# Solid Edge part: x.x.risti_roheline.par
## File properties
Author: Romil
Template: iso part.par
Last saved by: Romil
Revision: 43
Application: Solid Edge
Accuracy: 0.990
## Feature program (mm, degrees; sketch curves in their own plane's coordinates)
sketch for "unnamed Protrusion 1" plane through (0, 0, 0) normal (1, 0, 0) x-axis (0, 1, 0)
extrude "unnamed Protrusion 1" add finite 7.8 symmetric
sketch for "unnamed RevolvedCutout 1" plane through (0, 0, 0) normal (0, -1, 0) x-axis (1, 0, 0)
revolve "unnamed RevolvedCutout 1" cut finite 360 deg
sketch for "ExtrudedProtrusion_11" plane through (0, 0, 11.6) normal (0, 0, 1) x-axis (1, 0, 0)
extrude "ExtrudedProtrusion_11" add finite 6.8 along -normal
sketch for "unnamed Protrusion 2" plane through (0, 0, 11.6) normal (0, 0, 1) x-axis (1, 0, 0)
extrude "unnamed Protrusion 2" add finite 1.2 along -normal
sketch for "unnamed Protrusion 3" plane through (0, 0, 0) normal (0, 0, 1) x-axis (1, 0, 0)
extrude "unnamed Protrusion 3" add to key point along +normal
sketch for "unnamed Protrusion 4" plane through (0, 0, 0) normal (0, 0, 1) x-axis (1, 0, 0)
extrude "unnamed Protrusion 4" add to key point along +normal
mirror "unnamed Mirror 1" of "unnamed Protrusion 3" about plane through (0, 0, 0) normal (1, 0, 0)
extrude "unnamed Protrusion 5" add finite 4.8
sketch used by "unnamed Protrusion 6" plane through (0, 0, 0) normal (0, -1, 0) x-axis (1, 0, 0)
extrude "unnamed Protrusion 6" add to key point symmetric
sketch for "unnamed Cutout 1" plane through (0, 0, 11.6) normal (0, 0, 1) x-axis (1, 0, 0)
extrude "unnamed Cutout 1" cut to key point symmetric
sketch for "unnamed Cutout 2" plane through (0, 0, 0) normal (1, 0, 0) x-axis (0, 1, 0)
extrude "unnamed Cutout 2" cut finite 47.4999 symmetric
sketch for "ExtrudedCutout_25" plane through (0, 0, 0) normal (0, -1, 0) x-axis (1, 0, 0)
  circle centre (0, 0) radius 3.6
extrude "ExtrudedCutout_25" cut finite 152.9831 symmetric
sketch used by "ExtrudedCutout_26" plane through (0, 0, 0) normal (0, -1, 0) x-axis (1, 0, 0)
  line (0.6, 9.8798) -> (0.6, 5.3861)
  line (-0.6, 5.3861) -> (-0.6, 9.8798)
  line (0.6, 5.3861) -> (0.6, 4.8)
  line (0.6, 4.8) -> (-0.6, 4.8)
  line (-0.6, 4.8) -> (-0.6, 5.3861)
  line (-0.6, 9.8798) -> (-0.6, 10.4)
  line (-0.6, 10.4) -> (0.6, 10.4)
  line (0.6, 10.4) -> (0.6, 9.8798)
extrude "ExtrudedCutout_26" cut finite 35.3769 symmetric
fillet "unnamed Round 1"
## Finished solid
Body 1: solid body, 120 faces, 320 edges, 200 vertices.
  Faces by surface: cylinder 63, plane 43, blend 12, torus 2
  Edges by curve: line 170, circle 94, intersection 32, ellipse 24
Bounding box of the edges (mm; curved faces can reach further): 7.800 x 7.200 x 15.200, from (-3.9, -3.6, -3.6) to (3.9, 3.6, 11.6).
Cylindrical faces by radius (mm): R0.1 x8, R0.2 x8, R0.4 x24, R2.2319 x4, R2.35 x8, R2.7009 x2, R3.0587 x3, R3.6 x6
Toroidal faces (ring radius, tube radius in mm): R3.3 r0.3 x2
Planar faces by outward normal: +x 9, +y 6, +z 6, -x 9, -y 6, -z 7
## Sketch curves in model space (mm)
arc centre (0.975, -0.975, 11.6) radius 0.1 from (0.875, -0.975, 11.6) through (0.9064, -0.9023, 11.6) to (0.975, -0.875, 11.6)
line (0.975, -0.875, 11.6) -> (2.181, -0.875, 11.6)
arc centre (0, 0, 11.6) radius 2.35 from (2.181, 0.875, 11.6) through (2.35, 0, 11.6) to (2.181, -0.875, 11.6)
line (2.181, 0.875, 11.6) -> (0.975, 0.875, 11.6)
arc centre (0.975, 0.975, 11.6) radius 0.1 from (0.975, 0.875, 11.6) through (0.9023, 0.9064, 11.6) to (0.875, 0.975, 11.6)
line (0.875, 0.975, 11.6) -> (0.875, 2.181, 11.6)
arc centre (0, 0, 11.6) radius 2.35 from (-0.875, 2.181, 11.6) through (0, 2.35, 11.6) to (0.875, 2.181, 11.6)
line (-0.875, 2.181, 11.6) -> (-0.875, 0.975, 11.6)
arc centre (-0.975, 0.975, 11.6) radius 0.1 from (-0.875, 0.975, 11.6) through (-0.9064, 0.9023, 11.6) to (-0.975, 0.875, 11.6)
line (-0.975, 0.875, 11.6) -> (-2.181, 0.875, 11.6)
arc centre (0, 0, 11.6) radius 2.35 from (-2.181, -0.875, 11.6) through (-2.35, 0, 11.6) to (-2.181, 0.875, 11.6)
line (-2.181, -0.875, 11.6) -> (-0.975, -0.875, 11.6)
arc centre (-0.975, -0.975, 11.6) radius 0.1 from (-0.975, -0.875, 11.6) through (-0.9023, -0.9064, 11.6) to (-0.875, -0.975, 11.6)
line (-0.875, -0.975, 11.6) -> (-0.875, -2.181, 11.6)
arc centre (0, 0, 11.6) radius 2.35 from (0.875, -2.181, 11.6) through (0, -2.35, 11.6) to (-0.875, -2.181, 11.6)
line (0.875, -2.181, 11.6) -> (0.875, -0.975, 11.6)
circle centre (0, 0, 11.6) radius 2.7009
arc centre (-0.975, -0.975, 0) radius 0.1 from (-0.975, -0.875, 0) through (-0.9023, -0.9064, 0) to (-0.875, -0.975, 0)
line (-0.875, -0.975, 0) -> (-0.875, -2.181, 0)
arc centre (0, 0, 0) radius 2.35 from (0.875, -2.181, 0) through (0, -2.35, 0) to (-0.875, -2.181, 0)
line (0.875, -2.181, 0) -> (0.875, -0.975, 0)
arc centre (0.975, -0.975, 0) radius 0.1 from (0.875, -0.975, 0) through (0.9064, -0.9023, 0) to (0.975, -0.875, 0)
line (0.975, -0.875, 0) -> (2.181, -0.875, 0)
arc centre (0, 0, 0) radius 2.35 from (2.181, 0.875, 0) through (2.35, 0, 0) to (2.181, -0.875, 0)
line (2.181, 0.875, 0) -> (0.975, 0.875, 0)
arc centre (0.975, 0.975, 0) radius 0.1 from (0.975, 0.875, 0) through (0.9023, 0.9064, 0) to (0.875, 0.975, 0)
line (0.875, 0.975, 0) -> (0.875, 2.181, 0)
arc centre (0, 0, 0) radius 2.35 from (-0.875, 2.181, 0) through (0, 2.35, 0) to (0.875, 2.181, 0)
line (-0.875, 2.181, 0) -> (-0.875, 0.975, 0)
arc centre (-0.975, 0.975, 0) radius 0.1 from (-0.875, 0.975, 0) through (-0.9064, 0.9023, 0) to (-0.975, 0.875, 0)
line (-0.975, 0.875, 0) -> (-2.181, 0.875, 0)
arc centre (0, 0, 0) radius 2.35 from (-2.181, -0.875, 0) through (-2.35, 0, 0) to (-2.181, 0.875, 0)
line (-2.181, -0.875, 0) -> (-0.975, -0.875, 0)
arc centre (1.1947, 3.1832, 0) radius 0.2 from (1.3919, 3.2163, 0) through (1.349, 3.3104, 0) to (1.2649, 3.3705, 0)
arc centre (3.593, 3.586, 0) radius 2.2319 from (3.219, 1.3856, 0) through (1.9675, 2.0565, 0) to (1.3919, 3.2163, 0)
arc centre (3.1855, 1.1884, 0) radius 0.2 from (3.3729, 1.2583, 0) through (3.313, 1.3425, 0) to (3.219, 1.3856, 0)
arc centre (0, 0, 0) radius 3.6 from (3.3729, 1.2583, 0) through (3.6, 0, 0) to (3.3729, -1.2583, 0)
arc centre (3.1855, -1.1884, 0) radius 0.2 from (3.219, -1.3856, 0) through (3.313, -1.3425, 0) to (3.3729, -1.2583, 0)
arc centre (3.593, -3.586, 0) radius 2.2319 from (3.219, -1.3856, 0) through (1.9675, -2.0565, 0) to (1.3919, -3.2163, 0)
arc centre (1.1947, -3.1832, 0) radius 0.2 from (1.2649, -3.3705, 0) through (1.349, -3.3104, 0) to (1.3919, -3.2163, 0)
arc centre (0, 0, 0) radius 3.6 from (1.2649, -3.3705, 0) through (0, -3.6, 0) to (-1.2649, -3.3705, 0)
arc centre (-1.1947, -3.1832, 0) radius 0.2 from (-1.3919, -3.2163, 0) through (-1.349, -3.3104, 0) to (-1.2649, -3.3705, 0)
arc centre (-3.593, -3.586, 0) radius 2.2319 from (-3.219, -1.3856, 0) through (-1.9675, -2.0565, 0) to (-1.3919, -3.2163, 0)
arc centre (-3.1855, -1.1884, 0) radius 0.2 from (-3.3729, -1.2583, 0) through (-3.313, -1.3425, 0) to (-3.219, -1.3856, 0)
arc centre (0, 0, 0) radius 3.6 from (-3.3729, -1.2583, 0) through (-3.6, 0, 0) to (-3.3729, 1.2583, 0)
arc centre (-3.1855, 1.1884, 0) radius 0.2 from (-3.219, 1.3856, 0) through (-3.313, 1.3425, 0) to (-3.3729, 1.2583, 0)
arc centre (-3.593, 3.586, 0) radius 2.2319 from (-3.219, 1.3856, 0) through (-1.9675, 2.0565, 0) to (-1.3919, 3.2163, 0)
arc centre (-1.1947, 3.1832, 0) radius 0.2 from (-1.2649, 3.3705, 0) through (-1.349, 3.3104, 0) to (-1.3919, 3.2163, 0)
arc centre (0, 0, 0) radius 3.6 from (-1.2649, 3.3705, 0) through (0, 3.6, 0) to (1.2649, 3.3705, 0)
line (3.6217, 0, 4.8) -> (3.6217, 0, 3.8)
line (3.6217, 0, 3.8) -> (-3.6217, 0, 3.8)
line (-3.6217, 0, 3.8) -> (-3.6217, 0, 4.8)
line (-3.6217, 0, 4.8) -> (3.6217, 0, 4.8)
line (2.7, 0, -0.6) -> (2.7, 0, 0.6)
line (2.7, 0, 0.6) -> (-2.7, 0, 0.6)
line (-2.7, 0, 0.6) -> (-2.7, 0, -0.6)
line (-2.7, 0, -0.6) -> (2.7, 0, -0.6)
line (-3.35, -0.6, 0) -> (-3.35, 0.6, 0)
line (-3.35, 0.6, 0) -> (3.35, 0.6, 0)
line (3.35, 0.6, 0) -> (3.35, -0.6, 0)
line (3.35, -0.6, 0) -> (-3.35, -0.6, 0)
line (0.6, 0, 5.3861) -> (0.6, 0, 4.8)
line (0.6, 0, 4.8) -> (-0.6, 0, 4.8)
line (-0.6, 0, 4.8) -> (-0.6, 0, 5.3861)
line (-0.6, 0, 5.3861) -> (-0.6, 0, 9.8798)
line (-0.6, 0, 9.8798) -> (-0.6, 0, 10.4)
line (-0.6, 0, 10.4) -> (0.6, 0, 10.4)
line (0.6, 0, 10.4) -> (0.6, 0, 9.8798)
line (0.6, 0, 9.8798) -> (0.6, 0, 5.3861)
line (-4.4651, 0, 0) -> (5.0671, 0, 0)
line (2.7, 0, 3.0587) -> (2.7, 0, 3.3)
arc centre (3, 0, 3.3) radius 0.3 from (2.7, 0, 3.3) through (2.7941, 0, 3.5182) to (3, 0, 3.6)
line (3, 0, 3.6) -> (3.9, 0, 3.6)
line (3.9, 0, 3.6) -> (3.9, 0, 4.041)
line (3.9, 0, 4.041) -> (-3.9, 0, 4.041)
line (-3.9, 0, 4.041) -> (-3.9, 0, 3.6)
line (-3.9, 0, 3.6) -> (-3, 0, 3.6)
arc centre (-3, 0, 3.3) radius 0.3 from (-2.7, 0, 3.3) through (-2.7941, 0, 3.5182) to (-3, 0, 3.6)
line (-2.7, 0, 3.3) -> (-2.7, 0, 3.0587)
line (-2.7, 0, 3.0587) -> (2.7, 0, 3.0587)
circle centre (0, 0, 7.9783) radius 2.4
circle centre (0, 0, 7.9783) radius 3.6217
line (-3.6217, -2.75, 0) -> (-3.6217, 1.953, 0)
line (-3.6217, -2.75, 0) -> (-2.7879, -2.75, 0)
line (-2.7879, 2.75, 0) -> (-2.7879, -2.75, 0)
line (-3.6217, 2.75, 0) -> (-2.7879, 2.75, 0)
line (-3.6217, 2.75, 0) -> (-3.6217, 1.953, 0)
circle centre (0, 0, 0) radius 3.6
arc centre (3.593, -3.586, 11.6) radius 2.2319 from (3.219, -1.3856, 11.6) through (1.9675, -2.0565, 11.6) to (1.3919, -3.2163, 11.6)
arc centre (3.1855, -1.1884, 11.6) radius 0.2 from (3.219, -1.3856, 11.6) through (3.313, -1.3425, 11.6) to (3.3729, -1.2583, 11.6)
arc centre (0, 0, 11.6) radius 3.6 from (3.3729, 1.2583, 11.6) through (3.6, 0, 11.6) to (3.3729, -1.2583, 11.6)
arc centre (3.1855, 1.1884, 11.6) radius 0.2 from (3.3729, 1.2583, 11.6) through (3.313, 1.3425, 11.6) to (3.219, 1.3856, 11.6)
arc centre (3.593, 3.586, 11.6) radius 2.2319 from (3.219, 1.3856, 11.6) through (1.9675, 2.0565, 11.6) to (1.3919, 3.2163, 11.6)
arc centre (1.1947, 3.1832, 11.6) radius 0.2 from (1.3919, 3.2163, 11.6) through (1.349, 3.3104, 11.6) to (1.2649, 3.3705, 11.6)
arc centre (0, 0, 11.6) radius 3.6 from (-1.2649, 3.3705, 11.6) through (0, 3.6, 11.6) to (1.2649, 3.3705, 11.6)
arc centre (-1.1947, 3.1832, 11.6) radius 0.2 from (-1.2649, 3.3705, 11.6) through (-1.349, 3.3104, 11.6) to (-1.3919, 3.2163, 11.6)
arc centre (-3.593, 3.586, 11.6) radius 2.2319 from (-3.219, 1.3856, 11.6) through (-1.9675, 2.0565, 11.6) to (-1.3919, 3.2163, 11.6)
arc centre (-3.1855, 1.1884, 11.6) radius 0.2 from (-3.219, 1.3856, 11.6) through (-3.313, 1.3425, 11.6) to (-3.3729, 1.2583, 11.6)
arc centre (0, 0, 11.6) radius 3.6 from (-3.3729, -1.2583, 11.6) through (-3.6, 0, 11.6) to (-3.3729, 1.2583, 11.6)
arc centre (-3.1855, -1.1884, 11.6) radius 0.2 from (-3.3729, -1.2583, 11.6) through (-3.313, -1.3425, 11.6) to (-3.219, -1.3856, 11.6)
arc centre (-3.593, -3.586, 11.6) radius 2.2319 from (-3.219, -1.3856, 11.6) through (-1.9675, -2.0565, 11.6) to (-1.3919, -3.2163, 11.6)
arc centre (-1.1947, -3.1832, 11.6) radius 0.2 from (-1.3919, -3.2163, 11.6) through (-1.349, -3.3104, 11.6) to (-1.2649, -3.3705, 11.6)
arc centre (0, 0, 11.6) radius 3.6 from (1.2649, -3.3705, 11.6) through (0, -3.6, 11.6) to (-1.2649, -3.3705, 11.6)
arc centre (1.1947, -3.1832, 11.6) radius 0.2 from (1.2649, -3.3705, 11.6) through (1.349, -3.3104, 11.6) to (1.3919, -3.2163, 11.6)
circle centre (0, 0, 8) radius 3.6
arc centre (0, -0.975, -0.975) radius 0.1 from (0, -0.975, -0.875) through (0, -0.9023, -0.9064) to (0, -0.875, -0.975)
line (0, -0.875, -0.975) -> (0, -0.875, -2.181)
arc centre (0, 0, 0) radius 2.35 from (0, 0.875, -2.181) through (0, 0, -2.35) to (0, -0.875, -2.181)
line (0, 0.875, -2.181) -> (0, 0.875, -0.975)
arc centre (0, 0.975, -0.975) radius 0.1 from (0, 0.875, -0.975) through (0, 0.9064, -0.9023) to (0, 0.975, -0.875)
line (0, 0.975, -0.875) -> (0, 2.181, -0.875)
arc centre (0, 0, 0) radius 2.35 from (0, 2.181, 0.875) through (0, 2.35, 0) to (0, 2.181, -0.875)
line (0, 2.181, 0.875) -> (0, 0.975, 0.875)
arc centre (0, 0.975, 0.975) radius 0.1 from (0, 0.975, 0.875) through (0, 0.9023, 0.9064) to (0, 0.875, 0.975)
line (0, 0.875, 0.975) -> (0, 0.875, 2.181)
arc centre (0, 0, 0) radius 2.35 from (0, -0.875, 2.181) through (0, 0, 2.35) to (0, 0.875, 2.181)
line (0, -0.875, 2.181) -> (0, -0.875, 0.975)
arc centre (0, -0.975, 0.975) radius 0.1 from (0, -0.875, 0.975) through (0, -0.9064, 0.9023) to (0, -0.975, 0.875)
line (0, -0.975, 0.875) -> (0, -2.181, 0.875)
arc centre (0, 0, 0) radius 2.35 from (0, -2.181, -0.875) through (0, -2.35, 0) to (0, -2.181, 0.875)
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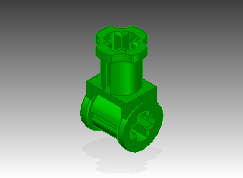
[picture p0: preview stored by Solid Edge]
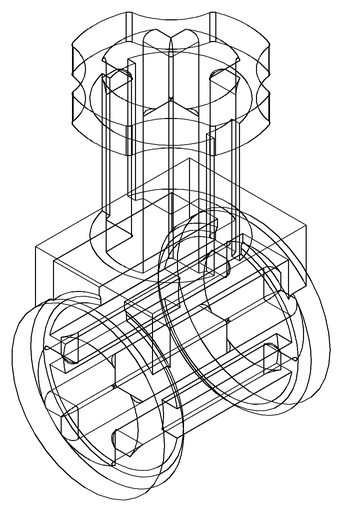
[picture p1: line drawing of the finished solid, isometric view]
